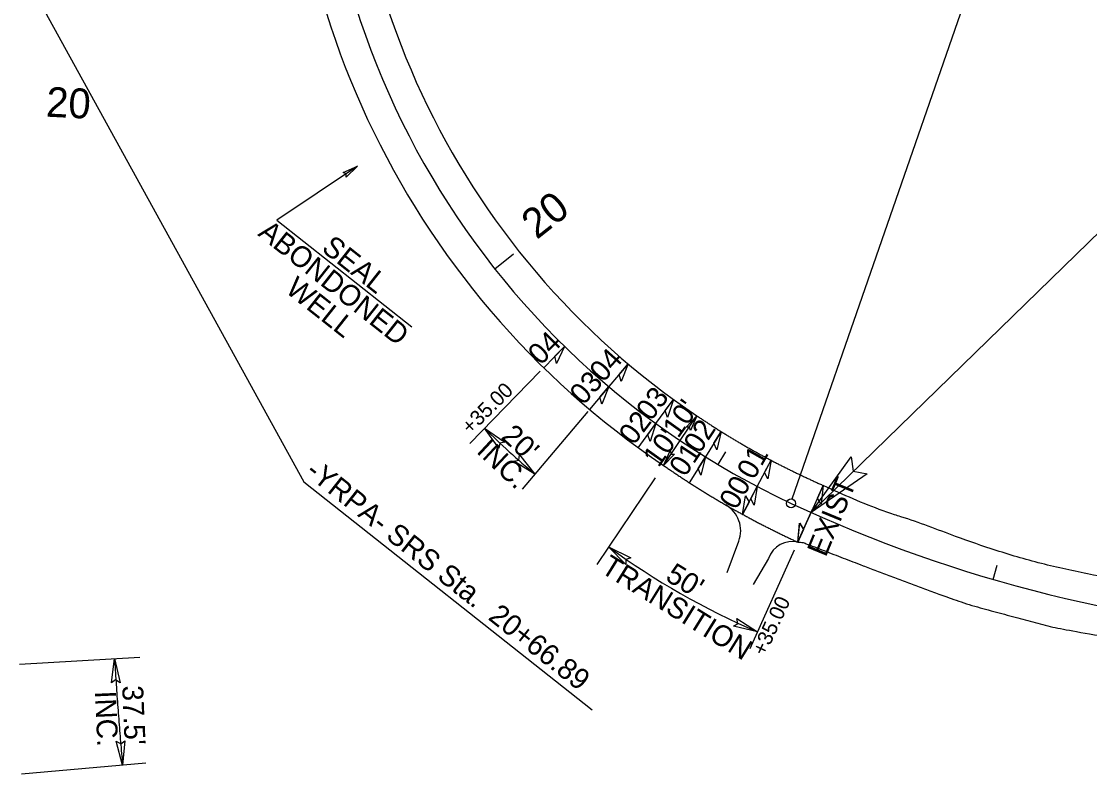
# Model space of a CAD drawing. Extents: x 1778969 to 1790720, y 807089 to 817794.
# Drawn here: x 1782468.8 to 1782826.4, y 813088.5 to 813338.7 of the extents above; entities that cross this region are included whole.
import ezdxf

# ---------------------------------------------------------------- set-up
doc = ezdxf.new("R2010")
doc.units = 0
for name, color, linetype in [('Prop Dimension', 7, 'Continuous'), ('Prop Dimension Text', 7, 'Continuous'), ('Prop DSN Text', 7, 'Continuous'), ('Prop EOT', 7, 'Continuous'), ('Prop Horizontal Alignment', 7, 'Continuous'), ('Prop Horizontal Alignment Station Label', 7, 'Continuous'), ('Prop Horizontal Alignment Tick Label', 7, 'Continuous'), ('Prop Horizontal Alignment Tick Large', 7, 'Continuous'), ('Prop Horizontal Alignment Tick Small', 7, 'Continuous'), ('Prop Superelevation  Arrow CELL', 7, 'Continuous'), ('Prop Superelevation Label', 7, 'Continuous'), ('Prop Terminator CELL', 7, 'Continuous')]:
    doc.layers.add(name, color=color, linetype=linetype)

msp = doc.modelspace()

# ---------------------------------------------------------------- linework, layer by layer
at = {"layer": 'Prop Dimension'}
for p, q in [((1782642.52, 813221.56), (1782618.9, 813197.43)), ((1782658.42, 813208.11), (1782636.45, 813182.12)), ((1782689.36, 813198.33), (1782694.95, 813206.63)), ((1782683.78, 813190.04), (1782689.36, 813198.33)), ((1782680.98, 813185.89), (1782661.43, 813156.86)), ((1782727.45, 813161.63), (1782712.65, 813128.66)), ((1782468.19, 813123.54), (1782508.45, 813125.86)), ((1782510.48, 813090.4), (1782468.92, 813086.63))]:
    msp.add_line(p, q, dxfattribs=at)
for centre, radius, start, end in [((1782842.99, 813426.42), 313.35, 225.6218, 229.7888), ((1782817.97, 813371.89), 258.89, 233.8878, 246.6038)]:
    msp.add_arc(centre, radius, start, end, dxfattribs=at)
msp.add_spline([(1782500.04, 813125.37), (1782500.1, 813124.41), (1782500.33, 813120.55), (1782500.57, 813116.69), (1782500.83, 813112.84), (1782501.11, 813108.99), (1782501.4, 813105.14), (1782501.7, 813101.3), (1782502.02, 813097.46), (1782502.35, 813093.63), (1782502.71, 813089.7)], degree=3, dxfattribs=at)
at = {"layer": 'Prop DSN Text'}
for p, q in [((1782581.31, 813290.23), (1782554.34, 813272.2)), ((1782554.34, 813272.2), (1782599.53, 813236.41))]:
    msp.add_line(p, q, dxfattribs=at)
at = {"layer": 'Prop EOT'}
for p, q in [((1782705.07, 813154.24), (1782708.95, 813164.66)), ((1782718.88, 813158.87), (1782713.77, 813150.15))]:
    msp.add_line(p, q, dxfattribs=at)
for centre, radius, start, end in [((1782842.99, 813426.42), 285, 173.9983, 236.0393), ((1782842.99, 813426.42), 265, 173.9983, 236.0393), ((1782699.58, 813168.15), 10, 339.5827, 60.0147), ((1782726.85, 813156.17), 8.41, 76.1204, 161.2759)]:
    msp.add_arc(centre, radius, start, end, dxfattribs=at)
for points in [[(1781718, 813799.07), (1781725.25, 813787.64), (1781732.32, 813776.09), (1781739.53, 813764.62), (1781748.41, 813750.49), (1781757.28, 813736.36), (1781766.17, 813722.23), (1781775.05, 813708.11), (1781784.04, 813694.06), (1781792.91, 813679.93), (1781801.78, 813665.79), (1781810.64, 813651.64), (1781819.51, 813637.51), (1781828.35, 813623.41), (1781837.2, 813609.31), (1781846.04, 813595.21), (1781854.91, 813581.09), (1781863.8, 813566.98), (1781872.77, 813552.92), (1781881.67, 813538.97), (1781890.62, 813525.06), (1781899.56, 813511.14), (1781909.02, 813496.43), (1781918.41, 813481.67), (1781927.98, 813467.03), (1781936.67, 813453.72), (1781945.44, 813440.46), (1781954.18, 813427.18), (1781963.4, 813413.19), (1781972.62, 813399.19), (1781981.85, 813385.2), (1781991.28, 813370.91), (1782000.79, 813356.66), (1782010.37, 813342.46), (1782019.44, 813329.02), (1782028.6, 813315.64), (1782037.78, 813302.29), (1782047.33, 813288.38), (1782056.88, 813274.48), (1782066.55, 813260.66), (1782076.08, 813247.05), (1782085.65, 813233.46), (1782095.22, 813219.88), (1782104.86, 813206.2), (1782114.49, 813192.52), (1782124.19, 813178.89), (1782133.79, 813165.38), (1782143.47, 813151.93), (1782153.2, 813138.53), (1782163.03, 813124.99), (1782172.87, 813111.45), (1782182.7, 813097.92), (1782192.49, 813084.44), (1782202.28, 813070.96), (1782212.1, 813057.5), (1782222.19, 813043.65), (1782232.6, 813030.04), (1782242.95, 813016.38), (1782253.03, 813003.08), (1782263.13, 812989.8), (1782273.21, 812976.5), (1782283.25, 812963.25), (1782293.24, 812949.97), (1782303.28, 812936.71), (1782313.15, 812923.68), (1782323.08, 812910.68), (1782333.22, 812897.85), (1782343.55, 812884.78), (1782353.98, 812871.79), (1782364.43, 812858.81), (1782374.92, 812845.79), (1782385.44, 812832.79), (1782395.93, 812819.76), (1782406.63, 812806.47), (1782417.16, 812793.03), (1782427.96, 812779.81), (1782438.52, 812766.89), (1782449.19, 812754.07), (1782459.83, 812741.21), (1782470.24, 812728.63), (1782480.58, 812715.98), (1782491.09, 812703.48), (1782501.82, 812690.7), (1782512.68, 812678.03), (1782523.5, 812665.33), (1782534.27, 812652.67), (1782545.05, 812640.01), (1782555.83, 812627.36), (1782566.67, 812614.64), (1782577.52, 812601.95), (1782588.45, 812589.31), (1782599.39, 812576.64), (1782610.53, 812564.14), (1782621.67, 812551.65), (1782632.74, 812539.22), (1782643.82, 812526.79), (1782655, 812514.46), (1782666.21, 812502.08), (1782677.45, 812489.72), (1782688.69, 812477.37), (1782699.92, 812465.03), (1782711.15, 812452.71), (1782722.41, 812440.4), (1782733.64, 812428.12), (1782744.98, 812415.94), (1782756.33, 812403.76), (1782767.99, 812391.23), (1782779.7, 812378.74), (1782791.5, 812366.34), (1782803.09, 812354.16), (1782814.85, 812342.15), (1782826.46, 812330), (1782838.01, 812317.9), (1782849.46, 812305.7), (1782861.02, 812293.59), (1782872.17, 812281.92), (1782883.35, 812270.25), (1782894.68, 812258.74), (1782906.41, 812246.83), (1782918.19, 812234.96), (1782929.97, 812223.1), (1782941.62, 812211.36), (1782953.24, 812199.57), (1782964.97, 812187.91), (1782968.29, 812184.62), (1782971.62, 812181.35), (1782974.95, 812178.08)], [(1782728.67, 813164.36), (1782729.5, 813164.34), (1782730.36, 813164.28), (1782731.14, 813163.98), (1782734.34, 813162.75), (1782737.52, 813161.5), (1782740.71, 813160.27), (1782743.9, 813159.03), (1782747.09, 813157.8), (1782750.28, 813156.56), (1782755.04, 813154.73), (1782759.82, 813152.96), (1782764.58, 813151.17), (1782769.35, 813149.38), (1782774.13, 813147.61), (1782778.93, 813145.89), (1782786.05, 813143.34), (1782793.37, 813141.42), (1782800.67, 813139.43), (1782807.35, 813137.62), (1782814.02, 813135.83), (1782820.82, 813134.61), (1782834.81, 813132.1), (1782848.84, 813130.01), (1782862.92, 813128.21), (1782866.45, 813127.76), (1782869.97, 813127.31), (1782873.5, 813126.88), (1782877.02, 813126.44), (1782880.54, 813126.01), (1782884.07, 813125.6), (1782891.12, 813124.77), (1782898.19, 813124.14), (1782905.28, 813123.85), (1782915.49, 813123.42), (1782925.71, 813123), (1782935.93, 813122.58)]]:
    msp.add_open_spline(points, degree=3, dxfattribs=at)
for points in [[(1782694.95, 813206.63), (1782695.49, 813206.26), (1782696.03, 813205.9), (1782696.57, 813205.54), (1782697.12, 813205.18), (1782697.66, 813204.82), (1782698.2, 813204.47), (1782698.75, 813204.11), (1782699.29, 813203.75), (1782699.84, 813203.4), (1782700.39, 813203.05), (1782700.94, 813202.7), (1782701.49, 813202.35), (1782702.04, 813202), (1782702.59, 813201.66), (1782703.14, 813201.31), (1782703.69, 813200.97), (1782704.25, 813200.62), (1782704.8, 813200.28), (1782705.36, 813199.94), (1782705.92, 813199.6), (1782706.47, 813199.27), (1782707.03, 813198.93), (1782707.59, 813198.6), (1782708.15, 813198.27), (1782708.71, 813197.93), (1782709.27, 813197.6), (1782709.83, 813197.27), (1782710.4, 813196.95), (1782710.96, 813196.62), (1782711.52, 813196.3), (1782712.09, 813195.97), (1782712.66, 813195.65), (1782713.22, 813195.33), (1782713.79, 813195.01), (1782714.36, 813194.69), (1782714.93, 813194.38), (1782715.5, 813194.06), (1782716.07, 813193.75), (1782716.64, 813193.44), (1782717.21, 813193.13), (1782717.79, 813192.82), (1782718.36, 813192.51), (1782718.93, 813192.2), (1782719.51, 813191.9), (1782720.09, 813191.6), (1782720.66, 813191.29), (1782721.24, 813190.99), (1782721.82, 813190.69), (1782722.4, 813190.4), (1782722.98, 813190.1), (1782723.56, 813189.8), (1782724.14, 813189.51), (1782724.72, 813189.22), (1782725.3, 813188.93), (1782725.89, 813188.64), (1782726.47, 813188.35), (1782727.06, 813188.06), (1782727.64, 813187.78), (1782728.23, 813187.5), (1782728.82, 813187.21), (1782729.4, 813186.93), (1782729.99, 813186.65), (1782730.58, 813186.38), (1782731.18, 813186.09), (1782731.78, 813185.81), (1782732.38, 813185.54), (1782732.98, 813185.26), (1782733.58, 813184.98), (1782734.18, 813184.7), (1782734.78, 813184.43), (1782735.38, 813184.15), (1782735.98, 813183.88), (1782737.19, 813183.33)], [(1782683.78, 813190.04), (1782684.35, 813189.64), (1782684.93, 813189.24), (1782685.51, 813188.84), (1782686.08, 813188.45), (1782686.66, 813188.05), (1782687.24, 813187.66), (1782687.82, 813187.27), (1782688.4, 813186.88), (1782688.99, 813186.49), (1782689.57, 813186.1), (1782690.15, 813185.71), (1782690.74, 813185.33), (1782691.33, 813184.95), (1782691.91, 813184.56), (1782692.5, 813184.18), (1782693.09, 813183.8), (1782693.68, 813183.43), (1782694.27, 813183.05), (1782694.87, 813182.68), (1782695.46, 813182.3), (1782696.05, 813181.93), (1782696.65, 813181.56), (1782697.24, 813181.19), (1782697.84, 813180.82), (1782698.44, 813180.46), (1782699.04, 813180.09), (1782699.64, 813179.73), (1782700.24, 813179.37), (1782700.84, 813179.01), (1782701.44, 813178.65), (1782702.05, 813178.29), (1782702.65, 813177.94), (1782703.26, 813177.58), (1782703.86, 813177.23), (1782704.47, 813176.88), (1782705.08, 813176.53), (1782705.69, 813176.18), (1782706.29, 813175.83), (1782706.91, 813175.49), (1782707.52, 813175.14), (1782708.13, 813174.8), (1782708.74, 813174.46), (1782709.36, 813174.12), (1782709.97, 813173.78), (1782710.59, 813173.45), (1782711.2, 813173.11), (1782711.82, 813172.78), (1782712.44, 813172.44), (1782713.06, 813172.11), (1782713.68, 813171.79), (1782714.3, 813171.46), (1782714.92, 813171.13), (1782715.54, 813170.81), (1782716.17, 813170.48), (1782716.79, 813170.16), (1782717.41, 813169.84), (1782718.04, 813169.52), (1782718.67, 813169.21), (1782719.29, 813168.89), (1782719.92, 813168.58), (1782720.55, 813168.27), (1782721.18, 813167.96), (1782721.81, 813167.65), (1782722.43, 813167.34), (1782723.05, 813167.04), (1782723.68, 813166.74), (1782724.3, 813166.44), (1782724.92, 813166.14), (1782725.55, 813165.84), (1782726.17, 813165.54), (1782726.79, 813165.24), (1782727.42, 813164.95), (1782728.67, 813164.36)], [(1782937.19, 813142.2), (1782917.53, 813142.95), (1782906.68, 813143.51), (1782895.85, 813144.31), (1782885.02, 813145.27), (1782874.19, 813146.32), (1782862.51, 813147.64), (1782850.87, 813149.27), (1782839.26, 813151.18), (1782827.68, 813153.35), (1782811.23, 813156.94), (1782795.08, 813161.58), (1782781.51, 813166.29), (1782763.16, 813172.88), (1782761.07, 813173.55), (1782741.06, 813181.55), (1782737.19, 813183.33)]]:
    msp.add_spline(points, degree=3, dxfattribs=at)
at = {"layer": 'Prop Horizontal Alignment'}
for centre, radius, start, end in [((1782842.99, 813426.42), 275, 173.9983, 244.9277), ((1788355.99, 817618.07), 7639.44, 213.341667, 236.008333), ((1782924.65, 813600.99), 467.72, 244.9277, 267.3909)]:
    msp.add_arc(centre, radius, start, end, dxfattribs=at)
at = {"layer": 'Prop Horizontal Alignment Station Label'}
for p, q in [((1782733.13, 813174.28), (1782984.95, 813419.67)), ((1782453.91, 813383.37), (1782563.37, 813184.58)), ((1782726.78, 813178.8), (1782798.2, 813384.5)), ((1782563.37, 813184.58), (1782659.84, 813108.2))]:
    msp.add_line(p, q, dxfattribs=at)
msp.add_circle((1782726.45, 813177.34), 1.5, dxfattribs=at)
at = {"layer": 'Prop Horizontal Alignment Tick Large'}
msp.add_line((1782627.26, 813255.87), (1782633.54, 813260.84), dxfattribs=at)
at = {"layer": 'Prop Horizontal Alignment Tick Small'}
for p, q in [((1782702.03, 813190.3), (1782704.59, 813194.59)), ((1782794.08, 813151.86), (1782795.47, 813156.66))]:
    msp.add_line(p, q, dxfattribs=at)
at = {"layer": 'Prop Superelevation  Arrow CELL'}
for p, q in [((1782643.66, 813222.72), (1782650.65, 813229.87)), ((1782671.9, 813224.05), (1782665.44, 813216.42)), ((1782665.44, 813216.42), (1782658.99, 813208.78)), ((1782681.17, 813204.07), (1782687.06, 813212.16)), ((1782675.29, 813195.98), (1782681.17, 813204.07)), ((1782703.03, 813201.38), (1782697.76, 813192.9)), ((1782697.76, 813192.9), (1782692.38, 813184.26)), ((1782715.11, 813182.96), (1782719.74, 813191.78)), ((1782737.19, 813183.33), (1782732.28, 813172.38)), ((1782737.19, 813183.33), (1782732.28, 813172.38)), ((1782710.22, 813173.65), (1782715.11, 813182.96)), ((1782728.67, 813164.36), (1782733.58, 813175.31)), ((1782728.7, 813164.41), (1782733.61, 813175.36))]:
    msp.add_line(p, q, dxfattribs=at)
for points in [[(1782650.65, 813229.87), (1782647.89, 813224.18), (1782647.42, 813226.57)], [(1782671.9, 813224.05), (1782669.55, 813218.18), (1782668.91, 813220.52)], [(1782665.44, 813216.42), (1782663.1, 813210.54), (1782662.46, 813212.88)], [(1782687.06, 813212.16), (1782685.14, 813206.13), (1782684.34, 813208.42)], [(1782681.17, 813204.07), (1782679.26, 813198.04), (1782678.45, 813200.33)], [(1782703.03, 813201.38), (1782701.56, 813195.23), (1782700.59, 813197.45)], [(1782697.76, 813192.9), (1782696.29, 813186.75), (1782695.32, 813188.97)], [(1782719.74, 813191.78), (1782718.72, 813185.54), (1782717.59, 813187.68)], [(1782737.19, 813183.33), (1782736.56, 813177.04), (1782735.29, 813179.11)], [(1782737.19, 813183.33), (1782736.56, 813177.04), (1782735.29, 813179.11)], [(1782710.22, 813173.65), (1782711.24, 813179.89), (1782712.37, 813177.74)], [(1782715.11, 813182.96), (1782714.09, 813176.72), (1782712.96, 813178.87)], [(1782728.67, 813164.36), (1782729.3, 813170.65), (1782730.56, 813168.58)], [(1782728.7, 813164.41), (1782729.33, 813170.71), (1782730.6, 813168.63)]]:
    msp.add_lwpolyline(points, close=True, dxfattribs=at)
at = {"layer": 'Prop Terminator CELL'}
for points in [[(1782576.5, 813288.09), (1782581.31, 813290.23), (1782577.49, 813286.57), (1782577.52, 813287.7)], [(1782691.33, 813202.81), (1782694.95, 813206.63), (1782692.82, 813201.78), (1782692.42, 813202.85)], [(1782628.66, 813195.81), (1782623.83, 813202.46), (1782630.67, 813197.81), (1782628.92, 813197.5)], [(1782687.41, 813193.84), (1782683.78, 813190.04), (1782685.93, 813194.88), (1782686.32, 813193.81)], [(1782635.55, 813193.55), (1782640.68, 813187.13), (1782633.64, 813191.46), (1782635.37, 813191.85)], [(1782751.94, 813187.21), (1782733.13, 813174.28), (1782746.53, 813192.94), (1782747.26, 813188.07)], [(1782671.14, 813156.87), (1782665.39, 813162.74), (1782672.84, 813159.14), (1782671.16, 813158.58)], [(1782708.31, 813138.81), (1782715.17, 813134.28), (1782707.13, 813136.23), (1782708.66, 813137.13)], [(1782499.02, 813117.22), (1782500.04, 813125.37), (1782501.85, 813117.3), (1782500.36, 813118.27)], [(1782503.43, 813097.88), (1782502.71, 813089.7), (1782500.6, 813097.69), (1782502.12, 813096.78)]]:
    msp.add_lwpolyline(points, close=True, dxfattribs=at)

# ---------------------------------------------------------------- texts
at = {"layer": 'Prop Dimension Text'}
for s, height, rotation, p in [('+35.00', 5, 44.462, (1782619.09, 813200.22)), ("10'", 7, 54.5461, (1782688.64, 813198.85)), ("20'", 7, 317.0509, (1782629.07, 813199.3)), ("10'", 7, 54.5461, (1782682.09, 813189.09)), ('INC.', 7, 317.0509, (1782620.82, 813194.45)), ('TRANSITION', 7, 328.1523, (1782662.34, 813154.46)), ("50'", 7, 328.1523, (1782684, 813151.81)), ('+35.00', 5, 65.1956, (1782717.69, 813125.96)), ("37.5'", 7, 272.4914, (1782502.56, 813116.26)), ('INC.', 7, 272.4914, (1782493.45, 813114.44))]:
    msp.add_text(s, height=height, rotation=rotation, dxfattribs=at).set_placement(p)
at = {"layer": 'Prop DSN Text'}
for s, p in [('ABONDONED', (1782547.67, 813267.21)), ('SEAL', (1782568.94, 813262.07)), ('WELL', (1782556.83, 813248.24))]:
    msp.add_text(s, height=7, rotation=321.6167, dxfattribs=at).set_placement(p)
at = {"layer": 'Prop Horizontal Alignment Station Label'}
msp.add_text('-YRPA- SRS Sta.  20+66.89', height=7, rotation=321.6398, dxfattribs=at).set_placement((1782563.55, 813187.13))
at = {"layer": 'Prop Horizontal Alignment Tick Label'}
for rotation, p in [(357.1377, (1782476.93, 813306.82)), (38.3296, (1782641.32, 813265.46))]:
    msp.add_text('20', height=10, rotation=rotation, dxfattribs=at).set_placement(p)
at = {"layer": 'Prop Superelevation Label'}
for s, rotation, p in [('04', 44.9975, (1782642.63, 813223.29)), ('04', 48.2208, (1782663.54, 813217.53)), ('03', 48.2208, (1782656.92, 813209.9)), ('03', 52.7519, (1782679.57, 813204.59)), ('02', 52.7519, (1782673.79, 813196.49)), ('02', 56.6963, (1782695.82, 813193.68)), ('01', 56.6963, (1782691, 813185.88)), ('01', 60.5673, (1782713.98, 813184.89)), ('00', 60.5673, (1782708.1, 813174.84)), ('EXIST', 67.659, (1782738.05, 813159.08))]:
    msp.add_text(s, height=7, rotation=rotation, dxfattribs=at).set_placement(p)

doc.saveas('drawing.dxf')
